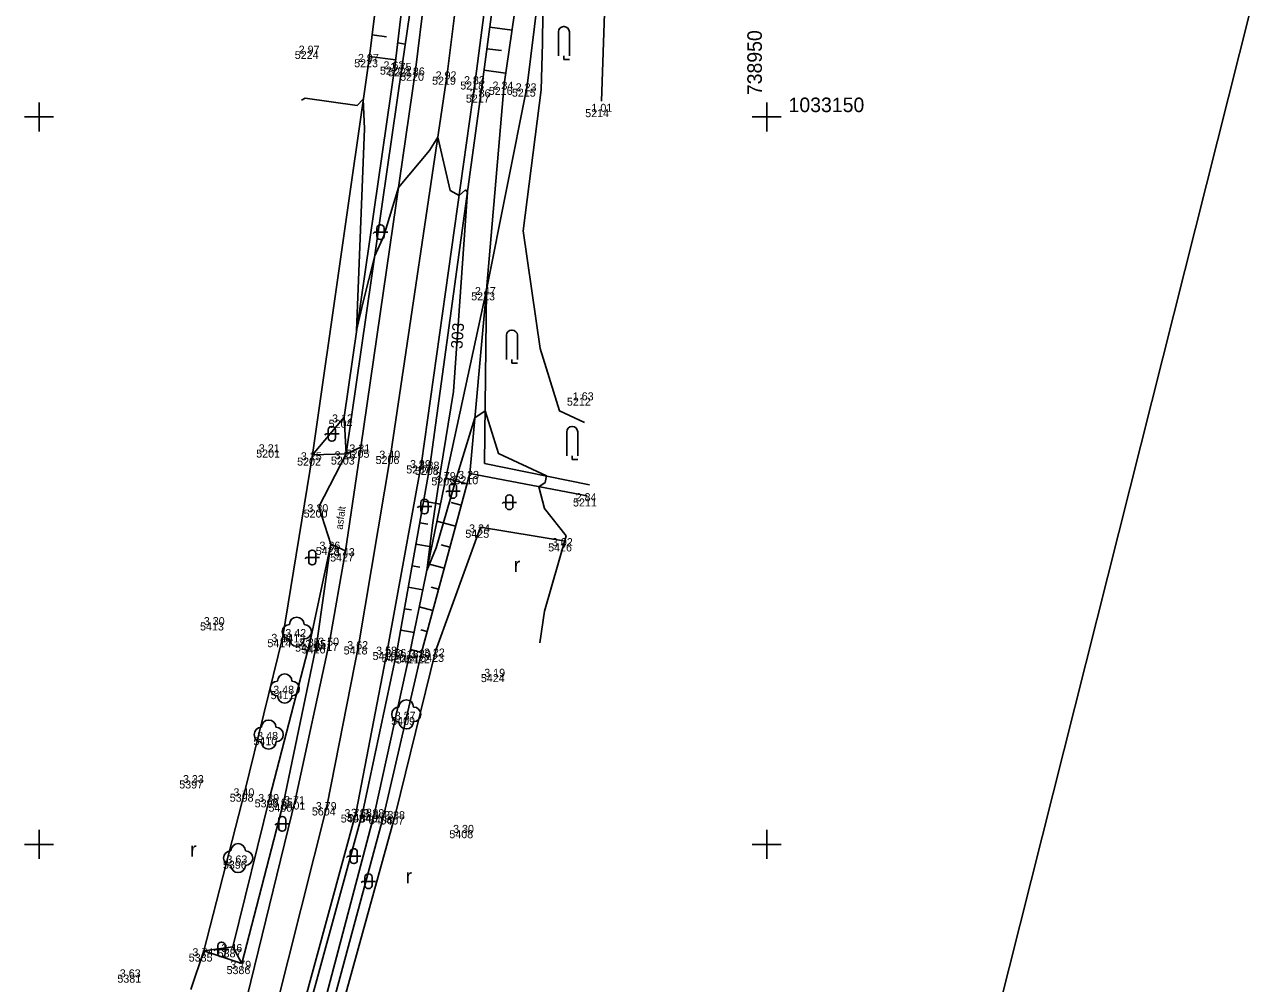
# Model space of a CAD drawing. Extents: x -740053 to -737517, y -1033516 to -1032488.
# Drawn here: x -739001 to -738916.8, y -1033209.6 to -1033143.6 of the extents above; entities that cross this region are included whole.
import ezdxf

# ---------------------------------------------------------------- set-up
doc = ezdxf.new("R2010")
doc.units = 0
for name, color, linetype in [('bod-cislo', 7, 'Continuous'), ('bod-oznac', 7, 'Continuous'), ('bod-vyska', 7, 'Continuous'), ('bod-vyska100', 7, 'Continuous'), ('Contours', 7, 'Continuous'), ('Contours text', 7, 'Continuous'), ('ctv-sit', 7, 'Continuous'), ('Hranice-zelene', 7, 'Continuous'), ('nazvy-bud-povr', 7, 'Continuous'), ('osa-komunikace', 7, 'Continuous'), ('Predmety bez rozlišeni', 7, 'Continuous'), ('Rozhrani-ploch', 7, 'Continuous'), ('rozhraní kultůr', 7, 'Continuous'), ('silnice', 7, 'Continuous'), ('Technické šrafy', 7, 'Continuous'), ('Terenni-hrana', 7, 'Continuous'), ('Znacky-kultury', 7, 'Continuous')]:
    doc.layers.add(name, color=color, linetype=linetype)

# ---------------------------------------------------------------- blocks, each defined once
blk = doc.blocks.new('POINT_DISPLAY')
blk.add_line((0, 0), (0, 0))
blk = doc.blocks.new('p_strom')
for centre, start, end in [((0, 1), 0, 180), ((-1, 0), 90, 270), ((1, 0), 270, 90), ((0, -1), 180, 0)]:
    blk.add_arc(centre, 1, start, end)
at = {"rotation": -180}
blk.add_blockref('POINT_DISPLAY', (0, 0), dxfattribs=at)
blk = doc.blocks.new('p_orna')
blk.add_text('r', height=2).set_placement((0, 0))
blk = doc.blocks.new('p_neplod')
for p, q in [((-0.82, 0), (-0.99, -0.18)), ((1, 0), (-0.82, 0)), ((-0.49, 0.56), (-0.49, -0.55)), ((0.05, 1.01), (-0.04, 1.01)), ((0.5, -0.55), (0.5, 0.56)), ((-0.04, -1), (0.05, -1))]:
    blk.add_line(p, q)
for centre, start, end in [((-0.04, 0.56), 90, 180), ((0.05, 0.56), 0, 90), ((-0.04, -0.55), 180, 270), ((0.05, -0.55), 270, 0)]:
    blk.add_arc(centre, 0.45, start, end)
blk = doc.blocks.new('p_leslis')
for p, q in [((-0.75, 0.5), (-0.75, 3.81)), ((-0.05, 4.51), (0.05, 4.51)), ((0.75, 0.5), (0.75, 3.81)), ((0, 0), (0, 0.5)), ((0, 0), (0.75, 0))]:
    blk.add_line(p, q)
for centre, start, end in [((-0.05, 3.81), 90, 180), ((0.05, 3.81), 0, 90)]:
    blk.add_arc(centre, 0.7, start, end)
blk = doc.blocks.new('ctvsit')
for p, q in [((0, -2), (0, 2)), ((2, 0), (-2, 0))]:
    blk.add_line(p, q)

msp = doc.modelspace()

# ---------------------------------------------------------------- linework, layer by layer
at = {"layer": 'Contours'}
for points in [[(-738961.356, -1033148.919), (-738960.789, -1033132.126), (-738960.707, -1033122.734), (-738959.893, -1033111.529), (-738958.828, -1033089.101), (-738958.367, -1033084.361), (-738958.045, -1033081.234), (-738956.873, -1033074.603), (-738956.556, -1033068.027), (-738956.642, -1033066.301), (-738956.552, -1033065.151), (-738956.313, -1033062.103), (-738955.277, -1033051.32), (-738953.402, -1033036.588), (-738952.723, -1033032.222), (-738952.594, -1033031.391)], [(-738962.524, -1033170.995), (-738964.232, -1033170.199), (-738965.578, -1033165.921), (-738966.733, -1033157.817), (-738965.508, -1033148.136), (-738965.4, -1033144.926), (-738965.346, -1033138.785)], [(-738965.587, -1033186.136), (-738965.269, -1033183.97), (-738963.789, -1033178.787), (-738965.268, -1033176.9), (-738965.651, -1033175.412), (-738965.233, -1033175.128), (-738965.133, -1033174.676), (-738968.426, -1033173.141), (-738969.351, -1033170.202), (-738970.062, -1033170.685), (-738971.246, -1033174.552), (-738972.718, -1033179.622), (-738973.362, -1033181.181), (-738972.937, -1033177.906), (-738972.409, -1033174.334), (-738971.514, -1033168.859), (-738970.565, -1033155.17), (-738970.703, -1033155.013), (-738971.136, -1033155.391), (-738971.746, -1033155.057), (-738972.605, -1033151.395), (-738973.176, -1033152.309), (-738975.307, -1033154.841), (-738976.318, -1033158.175), (-738976.937, -1033159.553), (-738977.746, -1033162.794), (-738978.18, -1033164.686), (-738977.648, -1033150.806), (-738977.72, -1033148.784), (-738978.151, -1033149.204), (-738981.713, -1033148.705), (-738981.963, -1033148.851)]]:
    msp.add_lwpolyline(points, dxfattribs=at)
at = {"layer": 'Hranice-zelene'}
for p, q in [((-738966.46, -1033147.87), (-738963.36, -1033122.59)), ((-738969.26, -1033161.87), (-738966.46, -1033147.87)), ((-738969.391, -1033173.818), (-738969.26, -1033161.87)), ((-738962.171, -1033175.273), (-738969.391, -1033173.818))]:
    msp.add_line(p, q, dxfattribs=at)
at = {"layer": 'osa-komunikace'}
for p, q in [((-738971.96, -1033147.05), (-738968.956, -1033122.817)), ((-738975.83, -1033173.12), (-738971.96, -1033147.05)), ((-738978.02, -1033186.21), (-738975.83, -1033173.12)), ((-738980.195, -1033197.276), (-738978.02, -1033186.21)), ((-738983.96, -1033212.16), (-738980.195, -1033197.276))]:
    msp.add_line(p, q, dxfattribs=at)
at = {"layer": 'Predmety bez rozlišeni'}
msp.add_line((-738916.757, -1033142.638), (-738942.39, -1033244.461), dxfattribs=at)
at = {"layer": 'Rozhrani-ploch'}
for p, q in [((-738980.77, -1033176.8), (-738978.9, -1033173.16)), ((-738978.9, -1033173.16), (-738977.89, -1033172.69)), ((-738979.94, -1033179.37), (-738980.77, -1033176.8)), ((-738978.95, -1033179.82), (-738979.94, -1033179.37))]:
    msp.add_line(p, q, dxfattribs=at)
at = {"layer": 'rozhraní kultůr'}
for p, q in [((-738972.76, -1033186.72), (-738969.66, -1033178.19)), ((-738969.66, -1033178.19), (-738963.97, -1033179.13)), ((-738975.5, -1033197.9), (-738972.76, -1033186.72)), ((-738979.71, -1033213.06), (-738975.5, -1033197.9))]:
    msp.add_line(p, q, dxfattribs=at)
at = {"layer": 'silnice'}
for p, q in [((-738974.14, -1033146.78), (-738971.18, -1033122.71)), ((-738970.01, -1033147.38), (-738966.81, -1033122.99)), ((-738977.89, -1033172.69), (-738974.14, -1033146.78)), ((-738973.72, -1033173.77), (-738970.01, -1033147.38)), ((-738978.95, -1033179.82), (-738977.89, -1033172.69)), ((-738976.05, -1033186.59), (-738973.72, -1033173.77)), ((-738980.03, -1033185.97), (-738978.95, -1033179.82)), ((-738982.37, -1033196.87), (-738980.03, -1033185.97)), ((-738978.22, -1033197.76), (-738976.05, -1033186.59)), ((-738985.96, -1033211.53), (-738982.37, -1033196.87)), ((-738982.24, -1033212.56), (-738978.22, -1033197.76))]:
    msp.add_line(p, q, dxfattribs=at)
at = {"layer": 'Technické šrafy'}
for p, q in [((-738969.024, -1033143.82), (-738967.502, -1033144.023)), ((-738977.114, -1033144.362), (-738976.122, -1033144.485)), ((-738974.836, -1033144.985), (-738975.355, -1033144.91)), ((-738969.223, -1033145.306), (-738968.232, -1033145.439)), ((-738977.3, -1033145.85), (-738975.496, -1033146.075)), ((-738969.421, -1033146.793), (-738967.938, -1033146.991)), ((-738970.603, -1033175.225), (-738972.06, -1033174.831)), ((-738973.58, -1033176.411), (-738972.425, -1033176.615)), ((-738970.994, -1033176.673), (-738971.678, -1033176.488)), ((-738973.841, -1033177.888), (-738973.284, -1033177.986)), ((-738971.385, -1033178.121), (-738972.663, -1033177.776)), ((-738974.103, -1033179.365), (-738973.028, -1033179.555)), ((-738971.776, -1033179.569), (-738972.37, -1033179.409)), ((-738974.364, -1033180.842), (-738973.847, -1033180.933)), ((-738972.166, -1033181.017), (-738973.267, -1033180.72)), ((-738974.626, -1033182.319), (-738973.631, -1033182.495)), ((-738972.557, -1033182.465), (-738973.063, -1033182.329)), ((-738974.887, -1033183.796), (-738974.41, -1033183.88)), ((-738972.948, -1033183.914), (-738973.871, -1033183.665)), ((-738975.149, -1033185.273), (-738974.234, -1033185.435)), ((-738973.339, -1033185.362), (-738973.756, -1033185.249)), ((-738973.73, -1033186.81), (-738974.475, -1033186.609))]:
    msp.add_line(p, q, dxfattribs=at)
at = {"layer": 'Terenni-hrana'}
for p, q in [((-738968.05, -1033147.75), (-738964.35, -1033122.58)), ((-738969.62, -1033148.28), (-738966.26, -1033123.13)), ((-738977.3, -1033145.85), (-738974.71, -1033125.1)), ((-738975.05, -1033146.47), (-738971.98, -1033125.2)), ((-738975.53, -1033146.36), (-738973.17, -1033126.82)), ((-738981.22, -1033173.23), (-738977.3, -1033145.85)), ((-738979.04, -1033170.63), (-738975.53, -1033146.36)), ((-738978.9, -1033173.16), (-738975.05, -1033146.47)), ((-738969.26, -1033161.87), (-738968.05, -1033147.75)), ((-738973.13, -1033173.87), (-738969.62, -1033148.28)), ((-738972.01, -1033174.59), (-738969.26, -1033161.87)), ((-738970.41, -1033174.51), (-738969.26, -1033161.87)), ((-738981.22, -1033173.23), (-738979.04, -1033170.63)), ((-738978.9, -1033173.16), (-738979.04, -1033170.63)), ((-738983.25, -1033185.71), (-738981.22, -1033173.23)), ((-738981.22, -1033173.23), (-738978.9, -1033173.16)), ((-738975.41, -1033186.75), (-738973.13, -1033173.87)), ((-738972.01, -1033174.59), (-738974.52, -1033186.83)), ((-738973.73, -1033186.81), (-738970.41, -1033174.51)), ((-738970.41, -1033174.51), (-738962.34, -1033176.04)), ((-738981.36, -1033186.02), (-738979.94, -1033179.37)), ((-738980.91, -1033186.14), (-738979.94, -1033179.37)), ((-738985.85, -1033196.33), (-738983.25, -1033185.71)), ((-738984.15, -1033196.72), (-738981.36, -1033186.02)), ((-738983.19, -1033197.02), (-738980.91, -1033186.14)), ((-738977.76, -1033197.73), (-738975.41, -1033186.75)), ((-738976.92, -1033197.76), (-738974.52, -1033186.83)), ((-738976.29, -1033197.88), (-738973.73, -1033186.81)), ((-738988.67, -1033207.32), (-738985.85, -1033196.33)), ((-738986.68, -1033207.03), (-738984.15, -1033196.72)), ((-738986.07, -1033208.18), (-738983.19, -1033197.02)), ((-738981.82, -1033212.6), (-738977.76, -1033197.73)), ((-738980.9, -1033212.76), (-738976.92, -1033197.76)), ((-738980.35, -1033212.95), (-738976.29, -1033197.88)), ((-738988.67, -1033207.32), (-738986.68, -1033207.03)), ((-738986.07, -1033208.18), (-738986.68, -1033207.03)), ((-738989.57, -1033209.98), (-738988.67, -1033207.32)), ((-738988.67, -1033207.32), (-738986.07, -1033208.18))]:
    msp.add_line(p, q, dxfattribs=at)

# ---------------------------------------------------------------- block references
at = {"layer": 'bod-oznac'}
for p in [(-738981.37, -1033145.28), (-738977.3, -1033145.85), (-738975.53, -1033146.36), (-738975.05, -1033146.47), (-738974.14, -1033146.78), (-738971.96, -1033147.05), (-738970.01, -1033147.38), (-738968.05, -1033147.75), (-738966.46, -1033147.87), (-738969.62, -1033148.28), (-738961.41, -1033149.28), (-738969.26, -1033161.87), (-738962.68, -1033169.11), (-738979.04, -1033170.63), (-738984.11, -1033172.68), (-738981.22, -1033173.23), (-738978.9, -1033173.16), (-738977.89, -1033172.69), (-738975.83, -1033173.12), (-738973.72, -1033173.77), (-738973.13, -1033173.87), (-738972.01, -1033174.59), (-738970.41, -1033174.51), (-738980.77, -1033176.8), (-738962.34, -1033176.04), (-738969.66, -1033178.19), (-738963.97, -1033179.13), (-738979.94, -1033179.37), (-738978.95, -1033179.82), (-738987.89, -1033184.56), (-738983.25, -1033185.71), (-738982.29, -1033185.38), (-738981.36, -1033186.02), (-738980.03, -1033185.97), (-738980.91, -1033186.14), (-738978.02, -1033186.21), (-738976.05, -1033186.59), (-738975.41, -1033186.75), (-738974.52, -1033186.83), (-738973.73, -1033186.81), (-738972.76, -1033186.72), (-738968.58, -1033188.11), (-738983.12, -1033189.28), (-738974.77, -1033191.06), (-738984.22, -1033192.45), (-738989.32, -1033195.42), (-738985.85, -1033196.33), (-738984.15, -1033196.72), (-738983.19, -1033197.02), (-738982.37, -1033196.87), (-738980.195, -1033197.276), (-738978.22, -1033197.76), (-738977.76, -1033197.73), (-738976.92, -1033197.76), (-738976.29, -1033197.88), (-738975.5, -1033197.9), (-738970.76, -1033198.84), (-738986.32, -1033200.94), (-738986.68, -1033207.03), (-738988.67, -1033207.32), (-738993.65, -1033208.77), (-738986.07, -1033208.18)]:
    msp.add_blockref('POINT_DISPLAY', p, dxfattribs=at)
at = {"layer": 'ctv-sit', "xscale": 0.5, "yscale": 0.5, "rotation": 180}
for p in [(-739000, -1033150), (-738950, -1033150), (-739000, -1033200), (-738950, -1033200)]:
    msp.add_blockref('ctvsit', p, dxfattribs=at)
at = {"layer": 'Znacky-kultury', "xscale": 0.5, "yscale": 0.5}
for name, p in [('p_leslis', (-738963.933, -1033146.044)), ('p_neplod', (-738976.542, -1033157.919)), ('p_leslis', (-738967.506, -1033166.912)), ('p_neplod', (-738979.88, -1033171.786)), ('p_leslis', (-738963.364, -1033173.535)), ('p_neplod', (-738971.559, -1033175.709)), ('p_neplod', (-738973.512, -1033176.779)), ('p_neplod', (-738967.688, -1033176.487)), ('p_neplod', (-738981.227, -1033180.284)), ('p_orna', (-738967.382, -1033181.279)), ('p_strom', (-738982.29, -1033185.38)), ('p_strom', (-738983.12, -1033189.28)), ('p_strom', (-738974.77, -1033191.06)), ('p_strom', (-738984.22, -1033192.45)), ('p_neplod', (-738983.29, -1033198.59)), ('p_orna', (-738989.623, -1033200.845)), ('p_strom', (-738986.32, -1033200.94)), ('p_neplod', (-738978.383, -1033200.8)), ('p_neplod', (-738977.371, -1033202.537)), ('p_orna', (-738974.814, -1033202.684)), ('p_neplod', (-738987.466, -1033207.228))]:
    msp.add_blockref(name, p, dxfattribs=at)

# ---------------------------------------------------------------- texts
at = {"layer": 'bod-cislo'}
for s, p in [('5224', (-738982.431, -1033146.013)), ('5223', (-738978.348, -1033146.583)), ('5222', (-738976.578, -1033147.093)), ('5221', (-738976.019, -1033147.203)), ('5220', (-738975.188, -1033147.513)), ('5219', (-738972.995, -1033147.783)), ('5218', (-738971.058, -1033148.113)), ('5216', (-738969.098, -1033148.483)), ('5215', (-738967.508, -1033148.603)), ('5217', (-738970.668, -1033149.013)), ('5214', (-738962.471, -1033150.013)), ('5213', (-738970.308, -1033162.603)), ('5212', (-738963.728, -1033169.843)), ('5204', (-738980.101, -1033171.363)), ('5201', (-738985.079, -1033173.413)), ('5202', (-738982.268, -1033173.963)), ('5203', (-738979.948, -1033173.893)), ('5205', (-738978.938, -1033173.423)), ('5206', (-738976.878, -1033173.853)), ('5207', (-738974.768, -1033174.503)), ('5208', (-738974.178, -1033174.603)), ('5209', (-738973.045, -1033175.323)), ('5210', (-738971.458, -1033175.243)), ('5211', (-738963.309, -1033176.773)), ('5200', (-738981.818, -1033177.533)), ('5425', (-738970.708, -1033178.923)), ('5426', (-738965.018, -1033179.863)), ('5428', (-738980.988, -1033180.103)), ('5427', (-738979.998, -1033180.553)), ('5413', (-738988.938, -1033185.293)), ('5414', (-738984.311, -1033186.443)), ('5412', (-738983.338, -1033186.113)), ('5415', (-738982.408, -1033186.753)), ('5416', (-738981.958, -1033186.873)), ('5417', (-738981.078, -1033186.703)), ('5418', (-738979.068, -1033186.943)), ('5419', (-738977.085, -1033187.323)), ('5423', (-738973.808, -1033187.453)), ('5420', (-738976.458, -1033187.483)), ('5421', (-738975.489, -1033187.563)), ('5422', (-738974.778, -1033187.543)), ('5424', (-738969.641, -1033188.843)), ('5411', (-738984.089, -1033190.013)), ('5409', (-738975.805, -1033191.793)), ('5410', (-738985.268, -1033193.183)), ('5397', (-738990.368, -1033196.153)), ('5398', (-738986.898, -1033197.063)), ('5399', (-738985.185, -1033197.453)), ('5400', (-738984.238, -1033197.753)), ('5401', (-738983.339, -1033197.603)), ('5604', (-738981.256, -1033198.009)), ('5403', (-738979.268, -1033198.493)), ('5404', (-738978.821, -1033198.463)), ('5405', (-738977.968, -1033198.493)), ('5406', (-738977.338, -1033198.613)), ('5407', (-738976.548, -1033198.633)), ('5408', (-738971.808, -1033199.573)), ('5396', (-738987.368, -1033201.673)), ('5385', (-738989.718, -1033208.053)), ('5387', (-738987.728, -1033207.763)), ('5386', (-738987.118, -1033208.913)), ('5381', (-738994.619, -1033209.503))]:
    msp.add_text(s, height=0.55, dxfattribs=at).set_placement(p)
at = {"layer": 'bod-vyska'}
for s, p in [('2 97', (-738982.159, -1033145.647)), ('2 97', (-738978.089, -1033146.217)), ('2 63', (-738976.332, -1033146.727)), ('2 75', (-738975.839, -1033146.837)), ('2 86', (-738974.929, -1033147.147)), ('2 92', (-738972.749, -1033147.417)), ('2 83', (-738970.799, -1033147.747)), ('2 86', (-738970.409, -1033148.647)), ('2 34', (-738968.839, -1033148.117)), ('2 23', (-738967.249, -1033148.237)), ('1 01', (-738962.042, -1033149.647)), ('2 47', (-738970.049, -1033162.237)), ('1 63', (-738963.325, -1033169.477)), ('3 12', (-738979.868, -1033170.997)), ('3 21', (-738984.899, -1033173.047)), ('3 31', (-738978.679, -1033173.057)), ('3 25', (-738982.009, -1033173.597)), ('3 26', (-738979.689, -1033173.527)), ('3 40', (-738976.619, -1033173.487)), ('3 39', (-738974.509, -1033174.137)), ('3 38', (-738973.919, -1033174.237)), ('2 79', (-738972.799, -1033174.957)), ('3 23', (-738971.199, -1033174.877)), ('2 84', (-738963.129, -1033176.407)), ('3 30', (-738981.559, -1033177.167)), ('3 24', (-738970.449, -1033178.557)), ('3 36', (-738980.729, -1033179.737)), ('3 02', (-738964.759, -1033179.497)), ('3 43', (-738979.739, -1033180.187)), ('3 30', (-738988.679, -1033184.927)), ('3 42', (-738983.079, -1033185.747)), ('3 40', (-738984.039, -1033186.077)), ('3 35', (-738982.149, -1033186.387)), ('3 45', (-738981.699, -1033186.507)), ('3 50', (-738980.819, -1033186.337)), ('3 62', (-738978.822, -1033186.577)), ('3 58', (-738976.839, -1033186.957)), ('3 56', (-738976.199, -1033187.117)), ('3 18', (-738975.348, -1033187.197)), ('3 30', (-738974.519, -1033187.177)), ('3 22', (-738973.549, -1033187.087)), ('3 19', (-738969.408, -1033188.477)), ('3 48', (-738983.909, -1033189.647)), ('3 37', (-738975.559, -1033191.427)), ('3 48', (-738985.009, -1033192.817)), ('3 33', (-738990.109, -1033195.787)), ('3 40', (-738986.639, -1033196.697)), ('3 39', (-738984.939, -1033197.087)), ('3 65', (-738983.992, -1033197.387)), ('3 71', (-738983.159, -1033197.237)), ('3 79', (-738980.984, -1033197.643)), ('3 71', (-738979.009, -1033198.127)), ('3 68', (-738978.562, -1033198.097)), ('3 38', (-738977.709, -1033198.127)), ('3 43', (-738977.079, -1033198.247)), ('3 38', (-738976.289, -1033198.267)), ('3 30', (-738971.549, -1033199.207)), ('3 63', (-738987.122, -1033201.307)), ('3 74', (-738989.459, -1033207.687)), ('3 46', (-738987.469, -1033207.397)), ('3 63', (-738994.452, -1033209.137)), ('3 79', (-738986.859, -1033208.547))]:
    msp.add_text(s, height=0.55, dxfattribs=at).set_placement(p)
at = {"layer": 'bod-vyska100'}
for s, p in [('302 97', (-738981.537, -1033145.313)), ('302 97', (-738977.467, -1033145.883)), ('302 63', (-738975.698, -1033146.393)), ('302 75', (-738975.217, -1033146.503)), ('302 86', (-738974.307, -1033146.813)), ('302 92', (-738972.127, -1033147.083)), ('302 83', (-738970.177, -1033147.413)), ('302 34', (-738968.217, -1033147.783)), ('302 23', (-738966.627, -1033147.903)), ('302 86', (-738969.787, -1033148.313)), ('301 01', (-738961.57, -1033149.313)), ('302 47', (-738969.427, -1033161.903)), ('301 63', (-738962.841, -1033169.143)), ('303 12', (-738979.211, -1033170.663)), ('303 21', (-738984.277, -1033172.713)), ('303 25', (-738981.387, -1033173.263)), ('303 26', (-738979.067, -1033173.193)), ('303 31', (-738978.057, -1033172.723)), ('303 40', (-738975.997, -1033173.153)), ('303 39', (-738973.887, -1033173.803)), ('303 38', (-738973.297, -1033173.903)), ('302 79', (-738972.177, -1033174.623)), ('303 23', (-738970.577, -1033174.543)), ('303 30', (-738980.937, -1033176.833)), ('302 84', (-738962.507, -1033176.073)), ('303 24', (-738969.827, -1033178.223)), ('303 02', (-738964.137, -1033179.163)), ('303 36', (-738980.107, -1033179.403)), ('303 43', (-738979.117, -1033179.853)), ('303 30', (-738988.057, -1033184.593)), ('303 40', (-738983.417, -1033185.743)), ('303 42', (-738982.457, -1033185.413)), ('303 35', (-738981.527, -1033186.053)), ('303 50', (-738980.197, -1033186.003)), ('303 45', (-738981.077, -1033186.173)), ('303 62', (-738978.188, -1033186.243)), ('303 58', (-738976.217, -1033186.623)), ('303 56', (-738975.577, -1033186.783)), ('303 18', (-738974.691, -1033186.863)), ('303 30', (-738973.897, -1033186.843)), ('303 22', (-738972.927, -1033186.753)), ('303 19', (-738968.751, -1033188.143)), ('303 48', (-738983.287, -1033189.313)), ('303 37', (-738974.937, -1033191.093)), ('303 48', (-738984.387, -1033192.483)), ('303 33', (-738989.487, -1033195.453)), ('303 40', (-738986.017, -1033196.363)), ('303 39', (-738984.317, -1033196.753)), ('303 65', (-738983.358, -1033197.053)), ('303 71', (-738982.537, -1033196.903)), ('303 79', (-738980.361, -1033197.31)), ('303 71', (-738978.387, -1033197.793)), ('303 68', (-738977.928, -1033197.763)), ('303 38', (-738977.087, -1033197.793)), ('303 43', (-738976.457, -1033197.913)), ('303 38', (-738975.667, -1033197.933)), ('303 30', (-738970.927, -1033198.873)), ('303 63', (-738986.488, -1033200.973)), ('303 46', (-738986.847, -1033207.063)), ('303 74', (-738988.837, -1033207.353)), ('303 63', (-738993.818, -1033208.803)), ('303 79', (-738986.237, -1033208.213))]:
    msp.add_text(s, height=0.05, dxfattribs=at).set_placement(p)
at = {"layer": 'Contours text'}
msp.add_text('303', height=0.8, rotation=86.03457, dxfattribs=at).set_placement((-738970.912, -1033165.958))
at = {"layer": 'ctv-sit'}
msp.add_text('738950', height=1, rotation=90, dxfattribs=at).set_placement((-738950.333, -1033148.5))
msp.add_text('1033150', height=1, dxfattribs=at).set_placement((-738948.5, -1033149.667))
at = {"layer": 'nazvy-bud-povr'}
msp.add_text('asfalt', height=0.5, rotation=82.54155, dxfattribs=at).set_placement((-738979.144, -1033178.382))

doc.saveas('drawing.dxf')
